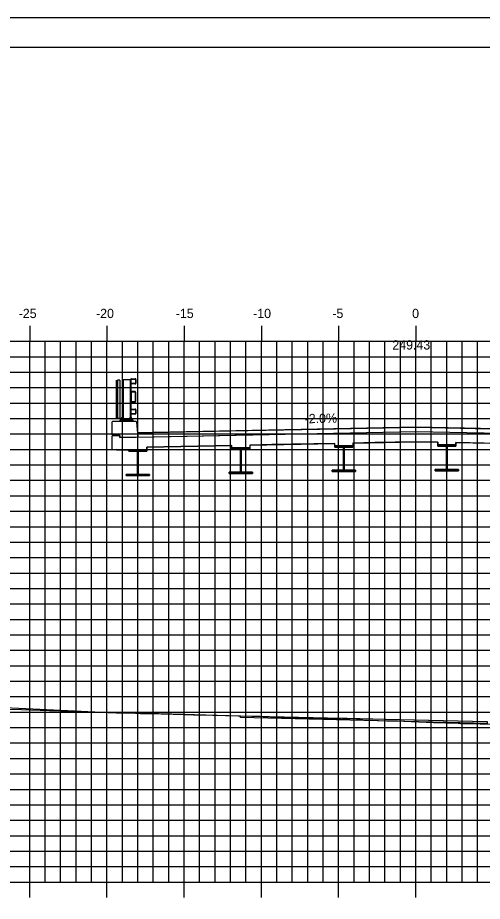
# Model space of a CAD drawing. Extents: x -22 to 1480, y -1511 to 8.
# Drawn here: x 605.9 to 636, y -1458.6 to -1401.4 of the extents above; entities that cross this region are included whole.
import ezdxf

# ---------------------------------------------------------------- set-up
doc = ezdxf.new("R2010")
doc.units = 0
for name, color, linetype in [('ANNOTATION', 7, 'Continuous'), ('BORDER', 7, 'Continuous'), ('D_Bridge_Deck', 7, 'Continuous'), ('D_Bridge_Railing', 7, 'Continuous'), ('D_Bridge_Superstructure', 7, 'Continuous'), ('D_Bridge_Superstructure_Slab', 7, 'Continuous'), ('D_Roadway_Centerline', 7, 'Continuous'), ('D_Roadway_Centerline_Text', 7, 'Continuous'), ('D_Roadway_Edge_Shoulder', 7, 'Continuous'), ('H_V ANNOTATION', 7, 'Continuous'), ('MAJOR', 7, 'Continuous'), ('MINOR', 7, 'Continuous'), ('PLOT BOUNDARY', 7, 'Continuous'), ('S_Roadway_Centerline', 7, 'Continuous')]:
    doc.layers.add(name, color=color, linetype=linetype)

msp = doc.modelspace()

# ---------------------------------------------------------------- linework, layer by layer
at = {"layer": 'BORDER'}
msp.add_line((716.67, -1403.331), (556.67, -1403.331), dxfattribs=at)
at = {"layer": 'D_Bridge_Deck'}
for p, q in [((612.503, -1428.429), (612.044, -1428.429)), ((612.503, -1428.554), (612.503, -1428.429))]:
    msp.add_line(p, q, dxfattribs=at)
for points in [[(612.044, -1428.429), (612.003, -1428.387), (612.003, -1427.551), (612.044, -1427.509), (613.544, -1427.509), (613.589, -1427.551), (613.669, -1428.53)], [(612.294, -1429.364), (613.003, -1429.364), (614.253, -1429.364)]]:
    msp.add_lwpolyline(points, dxfattribs=at)
at = {"layer": 'D_Bridge_Railing'}
for p, q in [((612.346, -1424.843), (612.346, -1427.334)), ((612.513, -1424.843), (612.346, -1424.843)), ((612.513, -1424.843), (612.513, -1427.334)), ((612.717, -1424.801), (612.717, -1427.333)), ((613.173, -1424.801), (613.173, -1427.333)), ((613.211, -1425.051), (613.211, -1424.801)), ((613.232, -1425.051), (613.232, -1424.801)), ((613.253, -1424.759), (613.503, -1424.759)), ((613.253, -1424.78), (613.503, -1424.78)), ((613.503, -1425.072), (613.253, -1425.072)), ((613.503, -1425.093), (613.253, -1425.093)), ((613.523, -1424.801), (613.523, -1425.051)), ((613.544, -1424.801), (613.544, -1425.051)), ((613.211, -1425.645), (613.211, -1426.207)), ((613.237, -1425.645), (613.237, -1426.207)), ((613.492, -1425.593), (613.263, -1425.593)), ((613.492, -1425.619), (613.263, -1425.619)), ((613.518, -1426.207), (613.518, -1425.645)), ((613.544, -1426.207), (613.544, -1425.645)), ((613.263, -1426.233), (613.492, -1426.233)), ((613.211, -1427.009), (613.211, -1426.759)), ((613.232, -1427.009), (613.232, -1426.759)), ((613.253, -1426.718), (613.503, -1426.718)), ((613.253, -1426.739), (613.503, -1426.739)), ((613.263, -1426.259), (613.492, -1426.259)), ((613.523, -1426.759), (613.523, -1427.009)), ((613.544, -1426.759), (613.544, -1427.009)), ((612.513, -1427.334), (612.346, -1427.334)), ((612.643, -1427.259), (612.716, -1427.259)), ((612.643, -1427.268), (612.716, -1427.268)), ((612.643, -1427.276), (612.716, -1427.276)), ((612.643, -1427.284), (612.716, -1427.284)), ((612.643, -1427.292), (612.716, -1427.292)), ((612.643, -1427.301), (612.716, -1427.301)), ((612.643, -1427.309), (612.716, -1427.309)), ((612.643, -1427.317), (612.716, -1427.317)), ((612.643, -1427.326), (612.716, -1427.326)), ((612.645, -1427.341), (612.645, -1427.397)), ((612.661, -1427.263), (612.698, -1427.263)), ((612.661, -1427.272), (612.698, -1427.272)), ((612.661, -1427.28), (612.698, -1427.28)), ((612.661, -1427.288), (612.698, -1427.288)), ((612.661, -1427.297), (612.698, -1427.297)), ((612.661, -1427.305), (612.698, -1427.305)), ((612.661, -1427.313), (612.698, -1427.313)), ((612.661, -1427.321), (612.698, -1427.321)), ((612.661, -1427.33), (612.698, -1427.33)), ((612.714, -1427.341), (612.714, -1427.397)), ((613.174, -1427.259), (613.247, -1427.259)), ((613.174, -1427.268), (613.247, -1427.268)), ((613.174, -1427.276), (613.247, -1427.276)), ((613.174, -1427.284), (613.247, -1427.284)), ((613.174, -1427.292), (613.247, -1427.292)), ((613.174, -1427.301), (613.247, -1427.301)), ((613.174, -1427.309), (613.247, -1427.309)), ((613.174, -1427.317), (613.247, -1427.317)), ((613.174, -1427.326), (613.247, -1427.326)), ((613.176, -1427.341), (613.176, -1427.397)), ((613.193, -1427.263), (613.229, -1427.263)), ((613.193, -1427.272), (613.229, -1427.272)), ((613.193, -1427.28), (613.229, -1427.28)), ((613.193, -1427.288), (613.229, -1427.288)), ((613.193, -1427.297), (613.229, -1427.297)), ((613.193, -1427.305), (613.229, -1427.305)), ((613.193, -1427.313), (613.229, -1427.313)), ((613.193, -1427.321), (613.229, -1427.321)), ((613.193, -1427.33), (613.229, -1427.33)), ((613.245, -1427.341), (613.245, -1427.397)), ((613.503, -1427.03), (613.253, -1427.03)), ((613.503, -1427.051), (613.253, -1427.051))]:
    msp.add_line(p, q, dxfattribs=at)
for points in [[(612.263, -1424.843), (612.263, -1427.334)], [(612.679, -1427.251), (612.679, -1424.801), (613.211, -1424.801), (613.211, -1427.251)], [(612.643, -1427.333), (612.643, -1427.259), (612.651, -1427.251), (612.708, -1427.251), (612.716, -1427.259), (612.716, -1427.333)], [(613.174, -1427.333), (613.174, -1427.259), (613.183, -1427.251), (613.239, -1427.251), (613.247, -1427.259), (613.247, -1427.333)]]:
    msp.add_lwpolyline(points, dxfattribs=at)
for points in [[(612.611, -1427.341), (612.624, -1427.333), (612.735, -1427.333), (612.749, -1427.341), (612.749, -1427.397), (612.735, -1427.405), (612.624, -1427.405), (612.611, -1427.397)], [(613.142, -1427.341), (613.156, -1427.333), (613.266, -1427.333), (613.28, -1427.341), (613.28, -1427.397), (613.266, -1427.405), (613.156, -1427.405), (613.142, -1427.397)], [(612.535, -1427.418), (613.355, -1427.418), (613.355, -1427.5), (612.535, -1427.5)], [(612.535, -1427.5), (613.355, -1427.5), (613.355, -1427.509), (612.535, -1427.509)], [(612.607, -1427.418), (612.753, -1427.418), (612.753, -1427.405), (612.607, -1427.405)], [(613.138, -1427.418), (613.284, -1427.418), (613.284, -1427.405), (613.138, -1427.405)]]:
    msp.add_lwpolyline(points, close=True, dxfattribs=at)
for centre, radius, start, end in [((613.253, -1424.801), 0.0417, 90, 180), ((613.253, -1425.051), 0.0417, 180, 270), ((613.253, -1424.801), 0.0208, 90, 180), ((613.253, -1425.051), 0.0208, 180, 270), ((613.503, -1424.801), 0.0417, 0, 90), ((613.503, -1424.801), 0.0208, 0, 90), ((613.503, -1425.051), 0.0417, 270, 0), ((613.503, -1425.051), 0.0208, 270, 0), ((613.263, -1425.645), 0.052, 90, 180), ((613.263, -1425.645), 0.026, 90, 180), ((613.492, -1425.645), 0.052, 0, 90), ((613.492, -1425.645), 0.026, 0, 90), ((613.263, -1426.207), 0.052, 180, 270), ((613.263, -1426.207), 0.026, 180, 270), ((613.492, -1426.207), 0.052, 270, 0), ((613.492, -1426.207), 0.026, 270, 0), ((613.253, -1426.759), 0.0417, 90, 180), ((613.253, -1426.759), 0.0208, 90, 180), ((613.503, -1426.759), 0.0417, 0, 90), ((613.503, -1426.759), 0.0208, 0, 90), ((612.628, -1427.366), 0.0302, 55.4339, 120), ((612.628, -1427.372), 0.0302, 240, 304.5661), ((612.68, -1427.45), 0.114, 72.412, 107.588), ((612.68, -1427.288), 0.114, 252.412, 287.588), ((612.731, -1427.366), 0.0302, 60, 124.5661), ((612.731, -1427.372), 0.0302, 235.4339, 300), ((613.159, -1427.366), 0.0302, 55.4339, 120), ((613.159, -1427.372), 0.0302, 240, 304.5661), ((613.211, -1427.45), 0.114, 72.412, 107.588), ((613.211, -1427.288), 0.114, 252.412, 287.588), ((613.253, -1427.009), 0.0417, 180, 270), ((613.253, -1427.009), 0.0208, 180, 270), ((613.262, -1427.366), 0.0302, 60, 124.5661), ((613.262, -1427.372), 0.0302, 235.4339, 300), ((613.503, -1427.009), 0.0417, 270, 0), ((613.503, -1427.009), 0.0208, 270, 0)]:
    msp.add_arc(centre, radius, start, end, dxfattribs=at)
at = {"layer": 'D_Bridge_Superstructure'}
for p, q in [((627.586, -1429.097), (626.419, -1429.097)), ((626.419, -1429.097), (626.419, -1429.18)), ((627.586, -1429.18), (627.586, -1429.097)), ((634.253, -1429.044), (633.086, -1429.044)), ((633.086, -1429.044), (633.086, -1429.127)), ((634.253, -1429.127), (634.253, -1429.044)), ((614.253, -1429.364), (613.086, -1429.364)), ((613.086, -1429.364), (613.086, -1429.447)), ((613.69, -1429.447), (613.648, -1429.447)), ((613.69, -1429.447), (613.648, -1429.447)), ((613.69, -1429.447), (614.253, -1429.447)), ((614.253, -1429.447), (614.253, -1429.364)), ((620.919, -1429.23), (619.753, -1429.23)), ((619.753, -1429.23), (619.753, -1429.314)), ((620.357, -1429.314), (620.315, -1429.314)), ((620.357, -1429.314), (620.315, -1429.314)), ((620.357, -1429.314), (620.919, -1429.314)), ((620.919, -1429.314), (620.919, -1429.23)), ((627.023, -1429.18), (626.982, -1429.18)), ((627.023, -1429.18), (626.982, -1429.18)), ((627.023, -1429.18), (627.586, -1429.18)), ((633.69, -1429.127), (633.648, -1429.127)), ((633.69, -1429.127), (633.648, -1429.127)), ((633.69, -1429.127), (634.253, -1429.127)), ((620.315, -1430.814), (619.586, -1430.814)), ((619.586, -1430.814), (619.586, -1430.897)), ((620.315, -1430.814), (619.586, -1430.814)), ((620.357, -1430.814), (620.315, -1430.814)), ((620.357, -1430.814), (620.315, -1430.814)), ((626.982, -1430.68), (626.253, -1430.68)), ((626.253, -1430.68), (626.253, -1430.764)), ((626.982, -1430.68), (626.253, -1430.68)), ((627.023, -1430.68), (626.982, -1430.68)), ((627.023, -1430.68), (626.982, -1430.68)), ((633.648, -1430.627), (632.919, -1430.627)), ((632.919, -1430.627), (632.919, -1430.71)), ((633.648, -1430.627), (632.919, -1430.627)), ((633.69, -1430.627), (633.648, -1430.627)), ((633.69, -1430.627), (633.648, -1430.627)), ((613.648, -1430.947), (612.919, -1430.947)), ((612.919, -1430.947), (612.919, -1431.03)), ((613.648, -1430.947), (612.919, -1430.947)), ((613.69, -1430.947), (613.648, -1430.947)), ((613.69, -1430.947), (613.648, -1430.947))]:
    msp.add_line(p, q, dxfattribs=at)
for points in [[(626.419, -1429.097), (627.586, -1429.097), (627.586, -1429.18), (626.419, -1429.18)], [(633.086, -1429.044), (634.253, -1429.044), (634.253, -1429.127), (633.086, -1429.127)], [(613.086, -1429.364), (614.253, -1429.364), (614.253, -1429.447), (613.086, -1429.447)], [(613.648, -1429.447), (613.69, -1429.447), (613.69, -1430.947), (613.648, -1430.947)], [(619.753, -1429.23), (620.919, -1429.23), (620.919, -1429.314), (619.753, -1429.314)], [(620.315, -1429.314), (620.357, -1429.314), (620.357, -1430.814), (620.315, -1430.814)], [(626.982, -1429.18), (627.023, -1429.18), (627.023, -1430.68), (626.982, -1430.68)], [(633.648, -1429.127), (633.69, -1429.127), (633.69, -1430.627), (633.648, -1430.627)], [(619.586, -1430.814), (621.086, -1430.814), (621.086, -1430.897), (619.586, -1430.897)], [(626.253, -1430.68), (627.753, -1430.68), (627.753, -1430.764), (626.253, -1430.764)], [(632.919, -1430.627), (634.419, -1430.627), (634.419, -1430.71), (632.919, -1430.71)], [(612.919, -1430.947), (614.419, -1430.947), (614.419, -1431.03), (612.919, -1431.03)]]:
    msp.add_lwpolyline(points, close=True, dxfattribs=at)
for points in [[(627.023, -1429.18), (627.586, -1429.18), (627.586, -1429.097), (626.419, -1429.097), (626.419, -1429.18), (626.982, -1429.18), (627.023, -1429.18)], [(633.69, -1429.127), (634.253, -1429.127), (634.253, -1429.044), (633.086, -1429.044), (633.086, -1429.127), (633.648, -1429.127), (633.69, -1429.127)], [(613.69, -1429.447), (614.253, -1429.447), (614.253, -1429.364), (613.086, -1429.364), (613.086, -1429.447), (613.648, -1429.447), (613.69, -1429.447)], [(613.086, -1429.447), (613.648, -1429.447), (613.69, -1429.447)], [(613.648, -1429.447), (613.648, -1430.947), (613.69, -1430.947), (613.69, -1429.447)], [(613.648, -1429.447), (613.648, -1430.947), (613.69, -1430.947), (613.69, -1429.447)], [(620.357, -1429.314), (620.919, -1429.314), (620.919, -1429.23), (619.753, -1429.23), (619.753, -1429.314), (620.315, -1429.314), (620.357, -1429.314)], [(619.753, -1429.314), (620.315, -1429.314), (620.357, -1429.314)], [(620.315, -1429.314), (620.315, -1430.814), (620.357, -1430.814), (620.357, -1429.314)], [(620.315, -1429.314), (620.315, -1430.814), (620.357, -1430.814), (620.357, -1429.314)], [(626.419, -1429.18), (626.982, -1429.18), (627.023, -1429.18)], [(626.982, -1429.18), (626.982, -1430.68), (627.023, -1430.68), (627.023, -1429.18)], [(626.982, -1429.18), (626.982, -1430.68), (627.023, -1430.68), (627.023, -1429.18)], [(633.086, -1429.127), (633.648, -1429.127), (633.69, -1429.127)], [(633.648, -1429.127), (633.648, -1430.627), (633.69, -1430.627), (633.69, -1429.127)], [(633.648, -1429.127), (633.648, -1430.627), (633.69, -1430.627), (633.69, -1429.127)], [(619.586, -1430.814), (619.586, -1430.897), (621.086, -1430.897), (621.086, -1430.814), (620.357, -1430.814)], [(619.586, -1430.897), (621.086, -1430.897), (621.086, -1430.814), (620.357, -1430.814)], [(626.253, -1430.68), (626.253, -1430.764), (627.753, -1430.764), (627.753, -1430.68), (627.023, -1430.68)], [(626.253, -1430.764), (627.753, -1430.764), (627.753, -1430.68), (627.023, -1430.68)], [(632.919, -1430.627), (632.919, -1430.71), (634.419, -1430.71), (634.419, -1430.627), (633.69, -1430.627)], [(632.919, -1430.71), (634.419, -1430.71), (634.419, -1430.627), (633.69, -1430.627)], [(612.919, -1430.947), (612.919, -1431.03), (614.419, -1431.03), (614.419, -1430.947), (613.69, -1430.947)], [(612.919, -1431.03), (614.419, -1431.03), (614.419, -1430.947), (613.69, -1430.947)]]:
    msp.add_lwpolyline(points, dxfattribs=at)
at = {"layer": 'D_Bridge_Superstructure_Slab'}
msp.add_line((631.669, -1428.837), (631.669, -1428.837), dxfattribs=at)
for points in [[(612.044, -1427.509), (613.544, -1427.509), (613.589, -1427.551), (613.669, -1428.53), (612.503, -1428.554), (612.503, -1428.429), (612.044, -1428.429), (612.003, -1428.387), (612.003, -1427.551)], [(613.647, -1428.26), (613.669, -1428.53), (631.669, -1428.17), (653.669, -1428.61), (653.691, -1428.34), (631.669, -1427.899)]]:
    msp.add_lwpolyline(points, close=True, dxfattribs=at)
for points in [[(637.003, -1428.944), (634.253, -1428.889), (634.253, -1429.044), (633.086, -1429.044), (633.086, -1428.865), (631.669, -1428.837), (630.336, -1428.864), (629.003, -1428.89), (627.586, -1428.919), (627.586, -1429.097), (626.419, -1429.097), (626.419, -1428.942), (622.336, -1429.024), (621.003, -1429.05), (620.919, -1429.052), (620.919, -1429.23), (619.753, -1429.23), (619.753, -1429.075), (614.253, -1429.185), (614.253, -1429.364), (612.294, -1429.364), (612.253, -1429.322), (612.253, -1429.364), (612.044, -1429.364), (612.003, -1429.322), (612.003, -1428.47), (612.044, -1428.429), (612.503, -1428.429), (612.503, -1428.554), (631.669, -1428.17), (654.836, -1428.634)], [(612.253, -1429.364), (612.044, -1429.364), (612.003, -1429.322), (612.003, -1428.47), (612.044, -1428.429)], [(612.503, -1428.554), (631.669, -1428.17), (654.836, -1428.634)], [(613.669, -1428.53), (622.169, -1428.36)], [(614.253, -1429.364), (614.253, -1429.185), (619.753, -1429.075)], [(620.919, -1429.052), (620.919, -1429.23), (619.753, -1429.23), (619.753, -1429.075)], [(620.919, -1429.052), (626.419, -1428.942)], [(627.586, -1428.919), (627.586, -1429.097), (626.419, -1429.097), (626.419, -1428.942)], [(627.586, -1428.919), (631.669, -1428.837), (633.086, -1428.865)], [(633.086, -1428.865), (633.086, -1429.044), (634.253, -1429.044), (634.253, -1428.889)], [(634.253, -1428.889), (639.753, -1428.999)], [(612.253, -1429.364), (612.253, -1429.322), (612.294, -1429.364)]]:
    msp.add_lwpolyline(points, dxfattribs=at)
at = {"layer": 'D_Roadway_Centerline'}
for points in [[(613.647, -1428.26), (616.669, -1428.199), (619.669, -1428.139), (625.429, -1428.024), (631.669, -1427.899), (637.429, -1428.015), (643.669, -1428.139), (648.669, -1428.239), (653.691, -1428.34)], [(603.701, -1446.092), (606.147, -1446.173), (607.957, -1446.233), (611.415, -1446.33), (612.544, -1446.366), (616.683, -1446.472), (616.704, -1446.473), (616.891, -1446.478), (617.31, -1446.49), (620.323, -1446.565), (621.565, -1446.597), (621.951, -1446.606), (625.531, -1446.695), (627.22, -1446.733), (630.568, -1446.808), (632.488, -1446.854), (636.276, -1446.939)]]:
    msp.add_lwpolyline(points, dxfattribs=at)
at = {"layer": 'D_Roadway_Edge_Shoulder'}
msp.add_lwpolyline([(620.323, -1446.565), (636.276, -1446.939), (636.276, -1447.064), (620.323, -1446.69)], close=True, dxfattribs=at)
at = {"layer": 'MAJOR'}
for p, q in [((606.669, -1421.329), (606.669, -1422.331)), ((611.669, -1421.329), (611.669, -1422.331)), ((616.669, -1421.329), (616.669, -1422.331)), ((621.669, -1421.329), (621.669, -1422.331)), ((626.669, -1421.329), (626.669, -1422.331)), ((631.669, -1421.329), (631.669, -1422.331)), ((561.669, -1422.331), (701.669, -1422.331)), ((561.669, -1422.331), (701.669, -1422.331)), ((606.669, -1457.331), (606.669, -1422.331)), ((611.669, -1457.331), (611.669, -1422.331)), ((616.669, -1457.331), (616.669, -1422.331)), ((621.669, -1457.331), (621.669, -1422.331)), ((626.669, -1457.331), (626.669, -1422.331)), ((631.669, -1457.331), (631.669, -1422.331)), ((561.669, -1427.331), (701.669, -1427.331)), ((561.669, -1432.331), (701.669, -1432.331)), ((561.669, -1437.331), (701.669, -1437.331)), ((561.669, -1442.331), (701.669, -1442.331)), ((561.669, -1447.331), (701.669, -1447.331)), ((561.669, -1452.331), (701.669, -1452.331)), ((561.669, -1457.331), (701.669, -1457.331)), ((561.669, -1457.331), (701.669, -1457.331)), ((606.669, -1458.333), (606.669, -1457.331)), ((611.669, -1458.333), (611.669, -1457.331)), ((616.669, -1458.333), (616.669, -1457.331)), ((621.669, -1458.333), (621.669, -1457.331)), ((626.669, -1458.333), (626.669, -1457.331)), ((631.669, -1458.333), (631.669, -1457.331))]:
    msp.add_line(p, q, dxfattribs=at)
at = {"layer": 'MINOR'}
for p, q in [((607.669, -1457.331), (607.669, -1422.331)), ((608.669, -1457.331), (608.669, -1422.331)), ((609.669, -1457.331), (609.669, -1422.331)), ((610.669, -1457.331), (610.669, -1422.331)), ((612.669, -1457.331), (612.669, -1422.331)), ((613.669, -1457.331), (613.669, -1422.331)), ((614.669, -1457.331), (614.669, -1422.331)), ((615.669, -1457.331), (615.669, -1422.331)), ((617.669, -1457.331), (617.669, -1422.331)), ((618.669, -1457.331), (618.669, -1422.331)), ((619.669, -1457.331), (619.669, -1422.331)), ((620.669, -1457.331), (620.669, -1422.331)), ((622.669, -1457.331), (622.669, -1422.331)), ((623.669, -1457.331), (623.669, -1422.331)), ((624.669, -1457.331), (624.669, -1422.331)), ((625.669, -1457.331), (625.669, -1422.331)), ((627.669, -1457.331), (627.669, -1422.331)), ((628.669, -1457.331), (628.669, -1422.331)), ((629.669, -1457.331), (629.669, -1422.331)), ((630.669, -1457.331), (630.669, -1422.331)), ((632.669, -1457.331), (632.669, -1422.331)), ((633.669, -1457.331), (633.669, -1422.331)), ((634.669, -1457.331), (634.669, -1422.331)), ((635.669, -1457.331), (635.669, -1422.331)), ((561.669, -1423.331), (701.669, -1423.331)), ((561.669, -1424.331), (701.669, -1424.331)), ((561.669, -1425.331), (701.669, -1425.331)), ((561.669, -1426.331), (701.669, -1426.331)), ((561.669, -1428.331), (701.669, -1428.331)), ((561.669, -1429.331), (701.669, -1429.331)), ((561.669, -1430.331), (701.669, -1430.331)), ((561.669, -1431.331), (701.669, -1431.331)), ((561.669, -1433.331), (701.669, -1433.331)), ((561.669, -1434.331), (701.669, -1434.331)), ((561.669, -1435.331), (701.669, -1435.331)), ((561.669, -1436.331), (701.669, -1436.331)), ((561.669, -1438.331), (701.669, -1438.331)), ((561.669, -1439.331), (701.669, -1439.331)), ((561.669, -1440.331), (701.669, -1440.331)), ((561.669, -1441.331), (701.669, -1441.331)), ((561.669, -1443.331), (701.669, -1443.331)), ((561.669, -1444.331), (701.669, -1444.331)), ((561.669, -1445.331), (701.669, -1445.331)), ((561.669, -1446.331), (701.669, -1446.331)), ((561.669, -1448.331), (701.669, -1448.331)), ((561.669, -1449.331), (701.669, -1449.331)), ((561.669, -1450.331), (701.669, -1450.331)), ((561.669, -1451.331), (701.669, -1451.331)), ((561.669, -1453.331), (701.669, -1453.331)), ((561.669, -1454.331), (701.669, -1454.331)), ((561.669, -1455.331), (701.669, -1455.331)), ((561.669, -1456.331), (701.669, -1456.331))]:
    msp.add_line(p, q, dxfattribs=at)
at = {"layer": 'PLOT BOUNDARY'}
msp.add_lwpolyline([(548.576, -1511.39), (718.576, -1511.39), (718.576, -1401.39), (548.576, -1401.39)], close=True, dxfattribs=at)
at = {"layer": 'S_Roadway_Centerline'}
msp.add_lwpolyline([(605.04, -1446.033), (605.975, -1446.073), (609.58, -1446.251), (611.74, -1446.361), (612.284, -1446.381), (613.514, -1446.411), (613.845, -1446.419), (615.177, -1446.452), (615.952, -1446.473), (617.269, -1446.504), (618.519, -1446.534), (620.166, -1446.576), (620.198, -1446.577), (620.323, -1446.58), (621.778, -1446.619), (622.74, -1446.658), (624.489, -1446.713), (625.725, -1446.754), (627.4, -1446.816), (628.032, -1446.835), (628.231, -1446.84), (629.775, -1446.891), (630.505, -1446.896), (630.894, -1446.912), (632.819, -1446.998), (634.405, -1447.055), (634.564, -1447.061), (635.04, -1447.077), (638.258, -1447.155)], dxfattribs=at)
msp.add_lwpolyline([(605.04, -1446.033), (605.975, -1446.073), (609.58, -1446.251), (611.74, -1446.361), (612.284, -1446.381), (613.514, -1446.411), (613.845, -1446.419), (615.177, -1446.452), (615.952, -1446.473), (617.269, -1446.504), (618.519, -1446.534), (620.166, -1446.576), (620.198, -1446.577), (620.323, -1446.58), (621.778, -1446.619), (622.74, -1446.658), (624.489, -1446.713), (625.725, -1446.754), (627.4, -1446.816), (628.032, -1446.835), (628.231, -1446.84), (629.775, -1446.891), (630.505, -1446.896), (630.894, -1446.912), (632.819, -1446.998), (634.405, -1447.055), (634.564, -1447.061), (635.04, -1447.077), (638.258, -1447.155)], dxfattribs=at)

# ---------------------------------------------------------------- texts
at = {"layer": 'ANNOTATION'}
msp.add_text('-2.0%', height=0.6, rotation=1.1458, dxfattribs=at).set_placement((624.473, -1427.643))
at = {"layer": 'D_Roadway_Centerline'}
for s, p in [('C', (631.664, -1427.899)), ('L', (631.669, -1427.907))]:
    msp.add_text(s, height=0.0146, dxfattribs=at).set_placement(p)
at = {"layer": 'D_Roadway_Centerline_Text'}
msp.add_text('249.43', height=0.6, dxfattribs=at).set_placement((630.147, -1422.867))
at = {"layer": 'H_V ANNOTATION'}
for s, p in [('-25', (605.955, -1420.831)), ('-20', (610.963, -1420.831)), ('-15', (616.126, -1420.831)), ('-10', (621.134, -1420.831)), ('-5', (626.26, -1420.831)), ('0', (631.429, -1420.831))]:
    msp.add_text(s, height=0.6, dxfattribs=at).set_placement(p)

doc.saveas('drawing.dxf')
